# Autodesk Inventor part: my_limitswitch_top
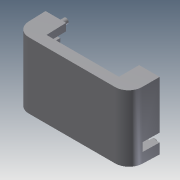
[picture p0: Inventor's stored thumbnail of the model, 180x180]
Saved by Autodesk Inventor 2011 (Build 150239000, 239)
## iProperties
Created: 2010-05
Part Number: my_limitswitch_top
Document SubType Name: Modeling
Designer: Phil
Density: 1 g/cm^3
Author: Phil
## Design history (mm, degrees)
sketch "Sketch1"
  geometry: L1 (0, 0)-(31.648, 0); L2 (31.648, 0)-(31.648, 18.491); L3 (31.648, 18.491)-(0, 18.491); L4 (0, 18.491)-(0, 0)
  constraints: 8 end point, 2 parallel, 1 horizontal, 1 perpendicular
  dimensions: "d0" = 31.6484 distance of L3.end L2.end; "d1" = 18.4912 distance of L2.end L1.end
extrude "Extrusion1" new body sketch "Sketch1" distance "d2" = 8.5598; taper "d3" = 1 deg
fillet "Fillet1" dims "d4" = 3.81
sketch "Sketch2"
  geometry: L1 (0.149, -0.149)-(-31.798, -0.149) reference; L2 (0.149, 18.641)-(0.149, -0.149) reference; L3 (-31.798, 18.641)-(0.149, 18.641) reference; L4 (-29.74, 1.908)-(-1.908, 1.908); L5 (-1.908, 1.908)-(-1.908, 9.192); L6 (-1.908, 9.192)-(-3.965, 9.192); L7 (-3.965, 9.192)-(-3.965, 14.145); L8 (-3.965, 14.145)-(-1.908, 14.145); L9 (-1.908, 14.145)-(-1.908, 16.583); L10 (-1.908, 16.583)-(-29.74, 16.583); L11 (-29.74, 16.583)-(-29.74, 14.145); L12 (-29.74, 14.145)-(-27.683, 14.145); L13 (-27.683, 14.145)-(-27.683, 9.192); L14 (-27.683, 9.192)-(-29.74, 9.192); L15 (-29.74, 9.192)-(-29.74, 1.908); 3 further points
  constraints: 24 end point, 10 parallel, 6 collinear, 2 midpoint, 1 perpendicular, 1 vertical alignment
  dimensions: "d5" = 2.0574 distance between parallel lines of L10 L3; "d6" = 2.4384 distance between parallel lines of L8 L10; "d7" = 4.953 distance between parallel lines of L6 L8; "d8" = 2.0574 distance between parallel lines of L2 L5 (= d5); "d9" = 2.0574 distance between parallel lines of L5 L7 (= d5); "d10" = 2.0574 distance between parallel lines of L1 L4 (= d5)
extrude "Extrusion2" cut sketch "Sketch2" distance "d11" = 6.5532; taper "d12" = 0 deg
sketch "Sketch3"
  geometry: L1 (-29.74, 1.908)-(-29.74, 9.192) reference; L2 (-31.798, -0.149)-(-31.798, 18.641) reference; L3 (0.149, -0.149)-(-31.798, -0.149) reference; L4 (-31.798, 5.134)-(-29.74, 5.134); L5 (-29.74, 2.746)-(-31.798, 2.746); 1 further point
  constraints: 4 end point, 4 point on line, 1 parallel, 1 perpendicular
  dimensions: "d13" = 2.8956 distance between parallel lines of L5 L3; "d14" = 2.3876 distance between parallel lines of L4 L5
extrude "Extrusion3" cut sketch "Sketch3" distance "d15" = 4.699; taper "d16" = 0 deg
sketch "Sketch5"
  geometry: L1 (28.054, -8.561)-(3.893, -8.561) reference; L2 (31.863, -4.817)-(31.947, 0) reference; L3 (31.947, 0)-(0, 0) reference; L4 (0.084, -4.817)-(0, 0) reference; L5 (26.205, 0)-(26.108, -5.563); L6 (26.108, -5.563)-(5.839, -5.563); L7 (5.839, -5.563)-(5.742, 0); 3 further points
  constraints: 6 end point, 3 parallel, 2 midpoint, 2 point on line, 1 vertical alignment
  dimensions: "d21" = 20.2692 distance of L5.end L6.end; "d22" = 5.5626 distance between parallel lines of L3 L6
extrude "Extrusion5" cut sketch "Sketch5" stored distance "d23" = 4.699; taper "d24" = 0 deg
sketch "Sketch6"
  geometry: L1 (-27.683, 9.192)-(-27.683, 14.145) reference; L2 (-3.965, 14.145)-(-3.965, 9.192) reference; 3 further points
  constraints: 2 midpoint
hole "Hole1" sketch "Sketch6" at (-27.683, 11.668), (-3.965, 11.668) diameter "d25" = 1.8542; stored, may be unused: countersink angle "d29" = 82 deg, drill point angle "d31" = 0 deg; dims "d26" = 19.05, "d27" = 2.8956, "d28" = 6.35, "d30" = 25.4
sketch "Sketch7"
  geometry: L1 (-31.798, -0.149)-(-31.798, 2.746) reference; L2 (0.149, -0.149)-(-31.798, -0.149) reference; L3 (0.149, 18.641)-(0.149, -0.149) reference; L4 (-5.593, 18.641)-(0.149, 18.641) reference; C1 r 0.749 at (-28.978, 0.841); C2 r 0.749 at (-4.067, 17.65); 1 further point
  constraints: 2 centre point
  dimensions: "d32" = 1.4986 diameter of C1; "d33" = 2.8194 distance from line of L1 C1.centre; "d34" = 0.9906 distance from line of L2 C1.centre; "d35" = 1.4986 diameter of C2; "d36" = 4.2164 distance from line of L3 C2.centre; "d37" = 0.9906 distance from line of L4 C2.centre
extrude "Extrusion6" join sketch "Sketch7" distance "d38" = 1.4986; taper "d39" = 0 deg
body "Solid1"
